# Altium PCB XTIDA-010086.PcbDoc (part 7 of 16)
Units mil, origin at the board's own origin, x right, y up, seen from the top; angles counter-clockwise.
Board outline 14763.78 x 8267.72 mil, 6 copper layers (Top Layer, GND Layer, Signal Layer 1, Signal Layer 2, Power Layer, Bottom Layer), stack 62 mil thick; 1933 components, 1002 nets, 4886 pads, 6482 vias.
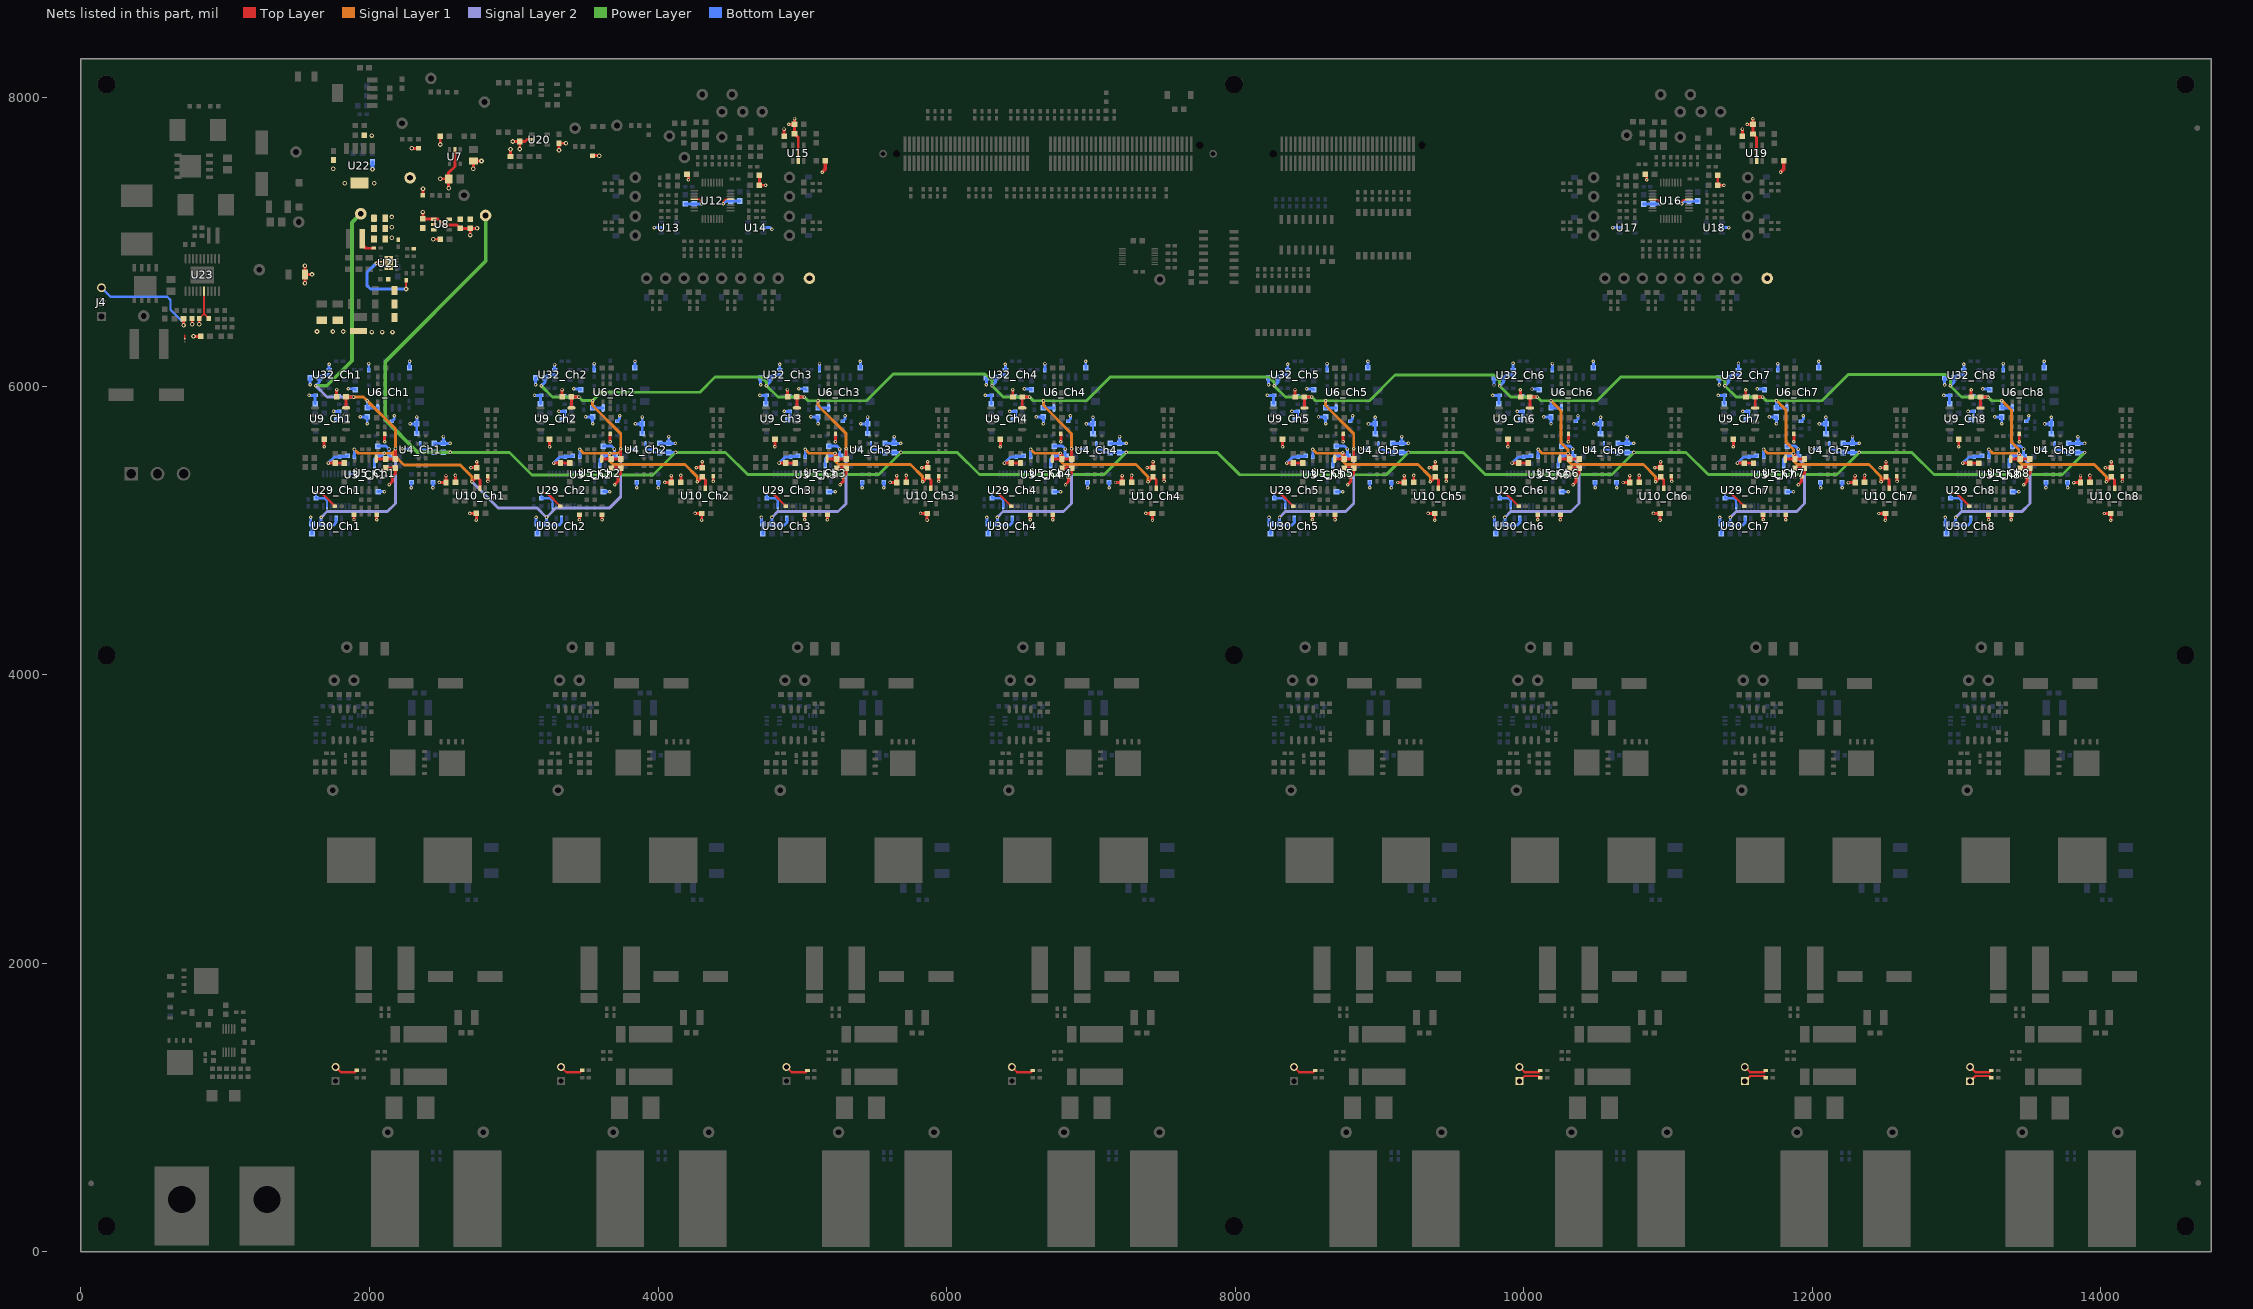
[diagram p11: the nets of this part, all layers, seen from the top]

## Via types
v1: diameter 32, hole 16, Top Layer to Bottom Layer, tented both sides, 4685 vias
v2: diameter 24, hole 12, Top Layer to Bottom Layer, tented both sides, 1013 vias
v3: diameter 32, hole 16, Top Layer to Bottom Layer, 728 vias
v4: diameter 19.68, hole 7.87, Top Layer to Bottom Layer, 40 vias
v5: diameter 214.57, hole 140, Top Layer to Bottom Layer, 16 vias

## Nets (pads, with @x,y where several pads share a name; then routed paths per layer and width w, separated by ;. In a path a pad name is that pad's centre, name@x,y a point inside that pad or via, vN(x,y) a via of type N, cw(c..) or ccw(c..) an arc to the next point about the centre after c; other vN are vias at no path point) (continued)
+VSense_Ch6: J2_Ch6.1 R14_Ch6.2 | length 166.4
  Top Layer w15: J2_Ch6.1@9969.7,1182.39 10006.41,1219.11 10103.21,1219.11 R14_Ch6.2@10115.71,1206.61
+VSense_Ch7: J2_Ch7.1 R14_Ch7.2 | length 166.4
  Top Layer w15: J2_Ch7.1@11531.7,1182.32 11568.41,1219.03 11665.21,1219.03 R14_Ch7.2@11677.71,1206.53
+VSense_Ch8: J2_Ch8.1 R14_Ch8.2 | length 166.4
  Top Layer w15: J2_Ch8.1@13093.7,1182.24 13130.41,1218.95 13227.21,1218.95 R14_Ch8.2@13239.71,1206.45
-2P5V: C39_Ch1.1 C39_Ch2.1 C39_Ch3.1 C39_Ch4.1 C39_Ch5.1 C39_Ch6.1 C39_Ch7.1 C39_Ch8.1 C43_Ch1.1 C43_Ch2.1 C43_Ch3.1 C43_Ch4.1 C43_Ch5.1 C43_Ch6.1 C43_Ch7.1 C43_Ch8.1 C133.1 C134.1 TP30.1 U4_Ch1.2 U4_Ch2.2 U4_Ch3.2 U4_Ch4.2 U4_Ch5.2 U4_Ch6.2 U4_Ch7.2 U4_Ch8.2 U8.5 | length 16495.8
  Power Layer w20: v2(2559.5,5540.2) 2969.8,5540.2 3127,5383 3964.37,5383 v2(4121.5,5540.13) 4467.87,5540.13 4622,5386 5529.45,5386 v2(5683.5,5540.05) 6073.95,5540.05 6227,5387 7092.53,5387 v2(7245.5,5539.97) 7876.03,5539.97 8031,5385 9046.31,5385 v2(9201.2,5539.89) 9580.11,5539.89 9733,5387 10610.39,5387 v2(10763.2,5539.81) 11125.19,5539.81 11279,5386 12171.46,5386 v2(12325.2,5539.73) 12689.27,5539.73 12843,5386 13733.54,5386 v2(13887.2,5539.65)
  Power Layer w25: v2(2559.5,5540.2) 2335.8,5540.2 2108.38,5767.62 2108.38,6167.38 2805,6864 TP30.1@2805,7182.7
  Bottom Layer w15: U4_Ch1.2@2352,5601.34 2352,5566.7 2359,5559.7 2393,5559.7 2412.5,5540.2 C43_Ch1.1@2449,5540.2 ; U4_Ch2.2@3914,5601.26 3914,5566.62 3921,5559.62 3955,5559.62 3974.5,5540.13 C43_Ch2.1@4011,5540.13 ; U4_Ch3.2@5476,5601.18 5476,5566.54 5483,5559.54 5517,5559.54 5536.5,5540.05 C43_Ch3.1@5573,5540.05 ; U4_Ch4.2@7038,5601.1 7038,5566.46 7045,5559.46 7079,5559.46 7098.5,5539.97 C43_Ch4.1@7135,5539.97 ; U4_Ch5.2@8993.7,5601.02 8993.7,5566.39 9000.7,5559.39 9034.7,5559.39 9054.2,5539.89 C43_Ch5.1@9090.7,5539.89 ; U4_Ch6.2@10555.7,5600.94 10555.7,5566.31 10562.7,5559.31 10596.7,5559.31 10616.2,5539.81 C43_Ch6.1@10652.7,5539.81 ; U4_Ch7.2@12117.7,5600.87 12117.7,5566.23 12124.7,5559.23 12158.7,5559.23 12178.2,5539.73 C43_Ch7.1@12214.7,5539.73 ; U4_Ch8.2@13679.7,5600.79 13679.7,5566.15 13686.7,5559.15 13720.7,5559.15 13740.2,5539.65 C43_Ch8.1@13776.7,5539.65
  Bottom Layer w20: C43_Ch1.1@2449,5540.2 C39_Ch1.1@2512.56,5540.2 v2(2559.5,5540.2) ; C43_Ch2.1@4011,5540.13 C39_Ch2.1@4074.56,5540.13 v2(4121.5,5540.13) ; C43_Ch3.1@5573,5540.05 C39_Ch3.1@5636.56,5540.05 v2(5683.5,5540.05) ; C43_Ch4.1@7135,5539.97 C39_Ch4.1@7198.56,5539.97 v2(7245.5,5539.97) ; C43_Ch5.1@9090.7,5539.89 C39_Ch5.1@9154.26,5539.89 v2(9201.2,5539.89) ; C43_Ch6.1@10652.7,5539.81 C39_Ch6.1@10716.26,5539.81 v2(10763.2,5539.81) ; C43_Ch7.1@12214.7,5539.73 C39_Ch7.1@12278.26,5539.73 v2(12325.2,5539.73) ; C43_Ch8.1@13776.7,5539.65 C39_Ch8.1@13840.26,5539.65 v2(13887.2,5539.65)
-5V: C18_Ch1.1 C18_Ch2.1 C18_Ch3.1 C18_Ch4.1 C18_Ch5.1 C18_Ch6.1 C18_Ch7.1 C18_Ch8.1 C20_Ch1.1 C20_Ch2.1 C20_Ch3.1 C20_Ch4.1 C20_Ch5.1 C20_Ch6.1 C20_Ch7.1 C20_Ch8.1 C33_Ch1.1 C33_Ch2.1 C33_Ch3.1 C33_Ch4.1 C33_Ch5.1 C33_Ch6.1 C33_Ch7.1 C33_Ch8.1 C40_Ch1.1 C40_Ch2.1 C40_Ch3.1 C40_Ch4.1 C40_Ch5.1 C40_Ch6.1 C40_Ch7.1 C40_Ch8.1 C45_Ch1.1 C45_Ch2.1 C45_Ch3.1 C45_Ch4.1 C45_Ch5.1 C45_Ch6.1 C45_Ch7.1 C45_Ch8.1 C47_Ch1.1 C47_Ch2.1 C47_Ch3.1 C47_Ch4.1 C47_Ch5.1 C47_Ch6.1 C47_Ch7.1 C47_Ch8.1 C131.1 C136_Ch1.1 C136_Ch2.1 C136_Ch3.1 C136_Ch4.1 C136_Ch5.1 C136_Ch6.1 C136_Ch7.1 C136_Ch8.1 C160.1 C161.1 C162.1 C166_Ch1.1 C166_Ch2.1 C166_Ch3.1 C166_Ch4.1 C166_Ch5.1 C166_Ch6.1 C166_Ch7.1 C166_Ch8.1 L6.2 R76_Ch1.2 R76_Ch2.2 R76_Ch3.2 R76_Ch4.2 R76_Ch5.2 R76_Ch6.2 R76_Ch7.2 R76_Ch8.2 R193_Ch1.1 R193_Ch2.1 R193_Ch3.1 R193_Ch4.1 R193_Ch5.1 R193_Ch6.1 R193_Ch7.1 R193_Ch8.1 R196.1 TP26.1 U3_Ch1.5 U3_Ch2.5 U3_Ch3.5 U3_Ch4.5 U3_Ch5.5 U3_Ch6.5 U3_Ch7.5 U3_Ch8.5 U5_Ch1.2 U5_Ch2.2 U5_Ch3.2 U5_Ch4.2 U5_Ch5.2 U5_Ch6.2 U5_Ch7.2 U5_Ch8.2 U6_Ch1.4 U6_Ch2.4 U6_Ch3.4 U6_Ch4.4 U6_Ch5.4 U6_Ch6.4 U6_Ch7.4 U6_Ch8.4 U8.2 U8.3 U9_Ch1.4 U9_Ch2.4 U9_Ch3.4 U9_Ch4.4 U9_Ch5.4 U9_Ch6.4 U9_Ch7.4 U9_Ch8.4 U10_Ch1.2 U10_Ch2.2 U10_Ch3.2 U10_Ch4.2 U10_Ch5.2 U10_Ch6.2 U10_Ch7.2 U10_Ch8.2 U30_Ch1.2 U30_Ch2.2 U30_Ch3.2 U30_Ch4.2 U30_Ch5.2 U30_Ch6.2 U30_Ch7.2 U30_Ch8.2 U32_Ch1.2 U32_Ch2.2 U32_Ch3.2 U32_Ch4.2 U32_Ch5.2 U32_Ch6.2 U32_Ch7.2 U32_Ch8.2 | length 41939.2
  Top Layer w20: C47_Ch1.1@1837.5,5924.7 C47_Ch1.1@1838.28,5923.91 ; U9_Ch1.4@1838.28,5848.55 C47_Ch1.1@1838.28,5923.91 ; v2(1889.79,5923.91) C47_Ch1.1@1838.28,5923.91 ; L6.2@1949.5,7020 1949.5,6979.5 1974,6955 2029.38,6955 R196.1@2031.38,6957 ; U3_Ch1.5@2047,5494.33 2113.79,5494.33 C20_Ch1.1@2114,5494.54 C18_Ch1.1@2180,5494.54 v2(2180,5566.49) ; v2(2710.25,5337.32) C45_Ch1.1@2744.6,5371.67 2766.54,5349.72 U10_Ch1.2@2766.54,5292.43 ; C47_Ch2.1@3399.5,5924.62 C47_Ch2.1@3400.28,5923.83 ; U9_Ch2.4@3400.28,5848.47 C47_Ch2.1@3400.28,5923.83 ; v2(3451.79,5923.83) C47_Ch2.1@3400.28,5923.83 ; U3_Ch2.5@3609,5494.25 3675.79,5494.25 C20_Ch2.1@3676,5494.46 C18_Ch2.1@3742,5494.46 v2(3742,5566.41) ; v2(4272.25,5337.24) C45_Ch2.1@4306.6,5371.59 4328.54,5349.65 U10_Ch2.2@4328.54,5292.35 ; C47_Ch3.1@4961.5,5924.54 C47_Ch3.1@4962.28,5923.76 ; U9_Ch3.4@4962.28,5848.39 C47_Ch3.1@4962.28,5923.76 ; v2(5013.79,5923.76) C47_Ch3.1@4962.28,5923.76 ; U3_Ch3.5@5171,5494.17 5237.79,5494.17 C20_Ch3.1@5238,5494.39 ; v2(5226.79,5534.54) 5238,5523.33 C20_Ch3.1@5238,5494.39 ; v2(5304,5566.33) C18_Ch3.1@5304,5494.39 C20_Ch3.1@5238,5494.39 ; v2(5834.25,5337.17) C45_Ch3.1@5868.6,5371.51 5890.54,5349.57 U10_Ch3.2@5890.54,5292.28 ; C47_Ch4.1@6523.5,5924.46 C47_Ch4.1@6524.28,5923.68 ; U9_Ch4.4@6524.28,5848.31 C47_Ch4.1@6524.28,5923.68 ; v2(6575.79,5923.68) C47_Ch4.1@6524.28,5923.68 ; U3_Ch4.5@6733,5494.09 6799.79,5494.09 C20_Ch4.1@6800,5494.31 ; v2(6788.79,5534.46) 6800,5523.25 C20_Ch4.1@6800,5494.31 ; v2(6866,5566.25) C18_Ch4.1@6866,5494.31 C20_Ch4.1@6800,5494.31 ; v2(7396.25,5337.09) C45_Ch4.1@7430.6,5371.43 7452.54,5349.49 U10_Ch4.2@7452.54,5292.2 ; C47_Ch5.1@8479.2,5924.39 C47_Ch5.1@8479.98,5923.6 ; U9_Ch5.4@8479.98,5848.24 C47_Ch5.1@8479.98,5923.6 ; v2(8531.49,5923.6) C47_Ch5.1@8479.98,5923.6 ; U3_Ch5.5@8688.7,5494.02 8755.49,5494.02 C20_Ch5.1@8755.7,5494.23 ; v2@8744.7,5536.39 8755.7,5525.39 C20_Ch5.1@8755.7,5494.23 ; v2(8821.7,5566.17) C18_Ch5.1@8821.7,5494.23 C20_Ch5.1@8755.7,5494.23 ; v2(9351.95,5337.01) C45_Ch5.1@9386.3,5371.36 9408.24,5349.41 U10_Ch5.2@9408.24,5292.12 ; C47_Ch6.1@10041.2,5924.31 C47_Ch6.1@10041.98,5923.52 ; U9_Ch6.4@10041.98,5848.16 C47_Ch6.1@10041.98,5923.52 ; v2(10093.49,5923.52) C47_Ch6.1@10041.98,5923.52 ; U3_Ch6.5@10250.7,5493.94 10317.49,5493.94 C20_Ch6.1@10317.7,5494.15 ; v2(10306.7,5532.31) 10317.7,5521.31 C20_Ch6.1@10317.7,5494.15 ; C18_Ch6.1@10383.7,5494.15 C20_Ch6.1@10317.7,5494.15 ; v2(10913.95,5336.93) C45_Ch6.1@10948.3,5371.28 10970.24,5349.33 U10_Ch6.2@10970.24,5292.04 ; C47_Ch7.1@11603.2,5924.23 C47_Ch7.1@11603.98,5923.44 ; U9_Ch7.4@11603.98,5848.08 C47_Ch7.1@11603.98,5923.44 ; v2(11655.49,5923.44) C47_Ch7.1@11603.98,5923.44 ; U3_Ch7.5@11812.7,5493.86 11879.49,5493.86 C20_Ch7.1@11879.7,5494.07 ; v2(11868.7,5532.23) 11879.7,5521.23 C20_Ch7.1@11879.7,5494.07 ; C18_Ch7.1@11945.7,5494.07 C20_Ch7.1@11879.7,5494.07 ; v2(12475.95,5336.85) C45_Ch7.1@12510.3,5371.2 12532.24,5349.25 U10_Ch7.2@12532.24,5291.96 ; C47_Ch8.1@13165.2,5924.15 C47_Ch8.1@13165.98,5923.36 ; U9_Ch8.4@13165.98,5848 C47_Ch8.1@13165.98,5923.36 ; v2(13217.49,5923.36) C47_Ch8.1@13165.98,5923.36 ; U3_Ch8.5@13374.7,5493.78 13441.49,5493.78 C20_Ch8.1@13441.7,5493.99 ; v2(13430.7,5532.15) 13436,5526.85 13436,5499.69 C20_Ch8.1@13441.7,5493.99 ; C18_Ch8.1@13507.7,5493.99 C20_Ch8.1@13441.7,5493.99 ; v2(14037.95,5336.77) C45_Ch8.1@14072.3,5371.12 14094.24,5349.17 U10_Ch8.2@14094.24,5291.88
  Power Layer w20: v2(3190.62,6001.68) 3268.46,5923.83 v2(3451.79,5923.83) ; v2@3451.79,5925.41 v2(3451.79,5923.83) ; v2(4750.73,6002.07) 4750.73,6028.27 4716,6063 4396,6063 4290,5957 3605.38,5957 v2(3547,5898.62) 3477,5898.62 v2(3451.79,5923.83) ; v2@4752.62,6001.6 4830.46,5923.76 v2(5013.79,5923.76) ; v2@5013.79,5925.33 v2(5013.79,5923.76) ; v2@6575.79,5925.25 v2(6575.79,5923.68) ; v2@8531.49,5925.17 v2(8531.49,5923.6) ; v2@10093.49,5925.09 v2(10093.49,5923.52) ; v2@11655.49,5925.02 v2(11655.49,5923.44) ; v2(13312.7,5898.15) 13242.7,5898.15 v2(13217.49,5923.36) 13034.17,5923.36 v2(12956.32,6001.2) 12956.32,6047.68 12924,6080 12249,6080 12067.23,5898.23 v2(11750.7,5898.23) 11680.7,5898.23 v2(11655.49,5923.44) ; v2(5013.79,5923.76) 5039,5898.54 v2(5109,5898.54) 5444.54,5898.54 5630,6084 6267,6084 6314.62,6036.38 v2(6314.62,6001.52) 6392.46,5923.68 v2(6575.79,5923.68) ; v2(6575.79,5923.68) 6601,5898.46 v2(6671,5898.46) 6969.46,5898.46 7133.94,6062.94 8234.06,6062.94 8270.32,6026.68 v2(8270.32,6001.44) 8348.17,5923.6 v2(8531.49,5923.6) ; v2(8531.49,5923.6) 8556.7,5898.39 v2(8626.7,5898.39) 8930.39,5898.39 9108,6076 9793,6076 9833.08,6035.92 v2(9833.08,6000.61) 9910.17,5923.52 v2(10093.49,5923.52) ; v2(10093.49,5923.52) 10118.7,5898.31 v2(10188.7,5898.31) 10507.31,5898.31 10673,6064 11362,6064 11394.32,6031.68 v2(11394.32,6001.28) 11472.17,5923.44 v2(11655.49,5923.44)
  Power Layer w25: v2(1628.38,6002) 1705,6002 1879,6176 1879,7133 TP26.1@1940,7194
  Signal Layer 1 w20: v2(1889.79,5923.91) 1959.79,5923.91 v2(1985,5898.7) 2180,5703.7 v2(2180,5566.49) 2180,5556 2158.7,5534.7 ; v2(1896,5561.07) 1922.37,5534.7 v2(2102.79,5534.7) 2158.7,5534.7 ; v2(2710.25,5337.32) 2710.25,5371.92 2629.17,5453 2240.4,5453 2158.7,5534.7 ; v2(3458,5561) 3484.37,5534.62 v2(3664.79,5534.62) ; v2(3547,5898.62) 3547,5865 3742,5670 v2(3742,5566.41) 3742,5550 3726.62,5534.62 v2(3664.79,5534.62) ; v2(4272.25,5337.24) 4272.25,5371.84 4188.09,5456 3689,5456 3664.79,5480.21 v2(3664.79,5534.62) ; v2(5020,5560.92) 5046.37,5534.54 v2(5226.79,5534.54) 5226.79,5480.13 5251,5455.92 5750.09,5455.92 5834.25,5371.77 v2(5834.25,5337.17) ; v2(5109,5898.54) 5109,5864.92 5304,5669.92 v2(5304,5566.33) ; v2(6582,5560.84) 6608.37,5534.46 v2(6788.79,5534.46) 6788.79,5480.06 6813,5455.84 7312.09,5455.84 7396.25,5371.69 v2(7396.25,5337.09) ; v2(6671,5898.46) 6671,5864.84 6866,5669.84 v2(6866,5566.25) ; v2(8537.7,5560.76) 8564.07,5534.39 8744.49,5534.39 8744.49,5479.98 8768.7,5455.76 9267.8,5455.76 9351.95,5371.61 v2(9351.95,5337.01) ; v2(8626.7,5898.39) 8626.7,5864.76 8821.7,5669.76 v2(8821.7,5566.17) ; v2(10099.7,5560.68) 10126.07,5534.31 10306.49,5534.31 10306.49,5479.9 10330.7,5455.69 10829.8,5455.69 10913.95,5371.53 v2(10913.95,5336.93) ; v2(10188.7,5898.31) 10256.7,5830.31 10256.7,5608.5 10306.7,5558.5 v2(10306.7,5532.31) ; v2(11661.7,5560.6) 11688.07,5534.23 v2@11868.49,5534.23 ; v2@11750.49,5900.23 11818.49,5832.23 11818.49,5610.42 11868.49,5560.42 v2@11868.49,5534.23 ; v2(12475.95,5336.85) 12475.95,5371.45 12391.8,5455.61 11892.7,5455.61 11868.49,5479.82 v2@11868.49,5534.23 ; v2(13223.7,5560.52) 13250.07,5534.15 v2@13430.49,5534.15 ; v2@13312.49,5900.15 13380.49,5832.15 13380.49,5610.34 13430.49,5560.34 v2@13430.49,5534.15 ; v2(14037.95,5336.77) 14037.95,5371.37 13953.8,5455.53 13454.7,5455.53 13430.49,5479.74 v2@13430.49,5534.15
  Signal Layer 2 w20: v2(1628.38,6002) 1706.46,5923.91 v2(1889.79,5923.91) ; v2(1665.5,5090) 1705.5,5130 2124,5130 2180,5186 v2(2180,5566.49) ; v2(2710.25,5337.32) 2891.57,5156 3161.42,5156 v2(3227.5,5089.92) 3293.57,5156 3665,5156 3742,5233 v2(3742,5566.41) ; v2(4789.5,5089.84) 4829.5,5129.84 5248,5129.84 5304,5185.84 v2(5304,5566.33) ; v2(6351.5,5089.76) 6391.5,5129.76 6810,5129.76 6866,5185.76 v2(6866,5566.25) ; v2(8307.2,5089.69) 8347.2,5129.69 8765.7,5129.69 8821.7,5185.69 v2(8821.7,5566.17) ; v2(9869.2,5089.61) 9909.2,5129.61 10327.7,5129.61 10383.7,5185.61 10383.7,5455.31 v2(10306.7,5532.31) ; v2(11431.2,5089.53) 11471.2,5129.53 11889.7,5129.53 11945.7,5185.53 11945.7,5455.23 v2(11868.7,5532.23) ; v2(12993.2,5089.45) 13033.2,5129.45 13451.7,5129.45 13507.7,5185.45 13507.7,5455.15 v2(13430.7,5532.15)
  Bottom Layer w20: v2(1628.38,6002) 1653.5,6027.12 C166_Ch1.1@1653.5,6057 1673.73,6077.24 U32_Ch1.2@1721.87,6077.24 ; v2@1665.5,5087.5 C136_Ch1.1@1665.5,5045 1672.5,5038 1753,5038 1769,5054 U30_Ch1.2@1769,5084.13 ; R76_Ch1.2@1786.62,5934.7 1797.41,5923.91 v2(1889.79,5923.91) ; R193_Ch1.1@1896,5509.62 v2(1896,5561.07) ; v2(1985,5898.7) C40_Ch1.1@1985,5849.54 1985.78,5848.76 U6_Ch1.4@2058,5848.76 ; U5_Ch1.2@2035,5449.18 2035,5495.55 C33_Ch1.1@2059,5519.55 2087.64,5519.55 v2(2102.79,5534.7) ; v2(3190.62,6001.68) 3215.74,6026.8 C166_Ch2.1@3215.74,6056.68 3235.98,6076.91 U32_Ch2.2@3284.11,6076.91 ; v2@3227.5,5087.43 C136_Ch2.1@3227.5,5044.92 3234.5,5037.92 3315,5037.92 3331,5053.92 U30_Ch2.2@3331,5084.06 ; R76_Ch2.2@3348.62,5934.62 3359.41,5923.83 v2(3451.79,5923.83) ; R193_Ch2.1@3458,5509.54 v2(3458,5561) ; v2(3547,5898.62) C40_Ch2.1@3547,5849.46 3547.78,5848.68 U6_Ch2.4@3620,5848.68 ; U5_Ch2.2@3597,5449.1 3597,5495.47 C33_Ch2.1@3621,5519.47 3649.64,5519.47 v2(3664.79,5534.62) ; v2(4750.73,6002.07) 4775.85,6027.19 C166_Ch3.1@4775.85,6057.07 4796.09,6077.31 U32_Ch3.2@4844.22,6077.31 ; v2@4789.5,5087.35 C136_Ch3.1@4789.5,5044.84 4796.5,5037.84 4877,5037.84 4893,5053.84 U30_Ch3.2@4893,5083.98 ; R76_Ch3.2@4910.62,5934.54 4921.41,5923.76 v2(5013.79,5923.76) ; R193_Ch3.1@5020,5509.46 v2(5020,5560.92) ; v2(5109,5898.54) C40_Ch3.1@5109,5849.39 5109.78,5848.61 U6_Ch3.4@5182,5848.61 ; U5_Ch3.2@5159,5449.02 5159,5495.39 C33_Ch3.1@5183,5519.39 5211.64,5519.39 v2(5226.79,5534.54) ; v2(6314.62,6001.52) 6339.74,6026.64 C166_Ch4.1@6339.74,6056.52 6359.98,6076.76 U32_Ch4.2@6408.11,6076.76 ; v2@6351.5,5087.27 C136_Ch4.1@6351.5,5044.76 6358.5,5037.76 6439,5037.76 6455,5053.76 U30_Ch4.2@6455,5083.9 ; R76_Ch4.2@6472.62,5934.46 6483.41,5923.68 v2(6575.79,5923.68) ; R193_Ch4.1@6582,5509.39 v2(6582,5560.84) ; v2(6671,5898.46) C40_Ch4.1@6671,5849.31 6671.78,5848.53 U6_Ch4.4@6744,5848.53 ; U5_Ch4.2@6721,5448.94 6721,5495.31 C33_Ch4.1@6745,5519.31 6773.64,5519.31 v2(6788.79,5534.46) ; v2(8270.32,6001.44) 8295.44,6026.56 C166_Ch5.1@8295.44,6056.44 8315.68,6076.68 U32_Ch5.2@8363.81,6076.68 ; v2@8307.2,5087.19 C136_Ch5.1@8307.2,5044.69 8314.2,5037.69 8394.7,5037.69 8410.7,5053.69 U30_Ch5.2@8410.7,5083.82 ; R76_Ch5.2@8428.32,5934.39 8439.11,5923.6 v2(8531.49,5923.6) ; R193_Ch5.1@8537.7,5509.31 v2(8537.7,5560.76) ; v2(8626.7,5898.39) C40_Ch5.1@8626.7,5849.23 8627.48,5848.45 U6_Ch5.4@8699.7,5848.45 ; U5_Ch5.2@8676.7,5448.87 8676.7,5495.24 C33_Ch5.1@8700.7,5519.24 8729.34,5519.24 8744.7,5534.6 v2(8744.7,5537.39) ; v2(9833.08,6000.61) 9858.2,6025.72 C166_Ch6.1@9858.2,6055.61 9878.43,6075.84 U32_Ch6.2@9926.57,6075.84 ; v2@9869.2,5087.11 C136_Ch6.1@9869.2,5044.61 9876.2,5037.61 9956.7,5037.61 9972.7,5053.61 U30_Ch6.2@9972.7,5083.74 ; R76_Ch6.2@9990.32,5934.31 10001.11,5923.52 v2(10093.49,5923.52) ; R193_Ch6.1@10099.7,5509.23 v2(10099.7,5560.68) ; v2(10188.7,5898.31) C40_Ch6.1@10188.7,5849.15 10189.48,5848.37 U6_Ch6.4@10261.7,5848.37 ; U5_Ch6.2@10238.7,5448.79 10238.7,5495.16 C33_Ch6.1@10262.7,5519.16 10291.34,5519.16 10306.49,5534.31 10306.7,5534.09 v2(10306.7,5532.31) ; v2(11394.32,6001.28) 11419.44,6026.4 C166_Ch7.1@11419.44,6056.28 11439.68,6076.52 U32_Ch7.2@11487.81,6076.52 ; v2@11431.2,5087.03 C136_Ch7.1@11431.2,5044.53 11438.2,5037.53 11518.7,5037.53 11534.7,5053.53 U30_Ch7.2@11534.7,5083.66 ; R76_Ch7.2@11552.32,5934.23 11563.11,5923.44 v2(11655.49,5923.44) ; R193_Ch7.1@11661.7,5509.15 v2(11661.7,5560.6) ; v2(11750.7,5898.23) C40_Ch7.1@11750.7,5849.07 11751.48,5848.29 U6_Ch7.4@11823.7,5848.29 ; U5_Ch7.2@11800.7,5448.71 11800.7,5495.08 C33_Ch7.1@11824.7,5519.08 11853.34,5519.08 11868.49,5534.23 11868.7,5534.02 v2(11868.7,5532.23) ; v2(12956.32,6001.2) 12981.44,6026.32 C166_Ch8.1@12981.44,6056.2 13001.68,6076.44 U32_Ch8.2@13049.81,6076.44 ; v2@12993.2,5086.95 C136_Ch8.1@12993.2,5044.45 13000.2,5037.45 13080.7,5037.45 13096.7,5053.45 U30_Ch8.2@13096.7,5083.58 ; R76_Ch8.2@13114.32,5934.15 13125.11,5923.36 v2(13217.49,5923.36) ; R193_Ch8.1@13223.7,5509.07 v2(13223.7,5560.52) ; v2(13312.7,5898.15) C40_Ch8.1@13312.7,5848.99 13313.48,5848.21 U6_Ch8.4@13385.7,5848.21 ; U5_Ch8.2@13362.7,5448.63 13362.7,5495 C33_Ch8.1@13386.7,5519 13415.34,5519 13430.49,5534.15 13430.7,5533.94 v2(13430.7,5532.15)
-VSense_Ch1: J2_Ch1.2 R17_Ch1.2 | length 166.4
  Top Layer w15: J2_Ch1.2@1766,1281.21 1802.71,1244.5 1899.51,1244.5 R17_Ch1.2@1912.01,1257
-VSense_Ch2: J2_Ch2.2 R17_Ch2.2 | length 166.4
  Top Layer w15: J2_Ch2.2@3328,1281.13 3364.71,1244.42 3461.51,1244.42 R17_Ch2.2@3474.01,1256.92
-VSense_Ch3: J2_Ch3.2 R17_Ch3.2 | length 166.4
  Top Layer w15: J2_Ch3.2@4890,1281.06 4926.71,1244.34 5023.51,1244.34 R17_Ch3.2@5036.01,1256.84
-VSense_Ch4: J2_Ch4.2 R17_Ch4.2 | length 166.4
  Top Layer w15: J2_Ch4.2@6452,1280.98 6488.71,1244.26 6585.51,1244.26 R17_Ch4.2@6598.01,1256.76
-VSense_Ch5: J2_Ch5.2 R17_Ch5.2 | length 166.4
  Top Layer w15: J2_Ch5.2@8407.7,1280.9 8444.41,1244.19 8541.21,1244.19 R17_Ch5.2@8553.71,1256.69
-VSense_Ch6: J2_Ch6.2 R17_Ch6.2 | length 166.4
  Top Layer w15: J2_Ch6.2@9969.7,1280.82 10006.41,1244.11 10103.21,1244.11 R17_Ch6.2@10115.71,1256.61
-VSense_Ch7: J2_Ch7.2 R17_Ch7.2 | length 166.4
  Top Layer w15: J2_Ch7.2@11531.7,1280.74 11568.41,1244.03 11665.21,1244.03 R17_Ch7.2@11677.71,1256.53
-VSense_Ch8: J2_Ch8.2 R17_Ch8.2 | length 166.4
  Top Layer w15: J2_Ch8.2@13093.7,1280.66 13130.41,1243.95 13227.21,1243.95 R17_Ch8.2@13239.71,1256.45
AGND: C18_Ch1.2 C18_Ch2.2 C18_Ch3.2 C18_Ch4.2 C18_Ch5.2 C18_Ch6.2 C18_Ch7.2 C18_Ch8.2 C20_Ch1.2 C20_Ch2.2 C20_Ch3.2 C20_Ch4.2 C20_Ch5.2 C20_Ch6.2 C20_Ch7.2 C20_Ch8.2 C21_Ch1.1 C21_Ch2.1 C21_Ch3.1 C21_Ch4.1 C21_Ch5.1 C21_Ch6.1 C21_Ch7.1 C21_Ch8.1 C22_Ch1.2 C22_Ch2.2 C22_Ch3.2 C22_Ch4.2 C22_Ch5.2 C22_Ch6.2 C22_Ch7.2 C22_Ch8.2 C23_Ch1.2 C23_Ch2.2 C23_Ch3.2 C23_Ch4.2 C23_Ch5.2 C23_Ch6.2 C23_Ch7.2 C23_Ch8.2 C24_Ch1.2 C24_Ch2.2 C24_Ch3.2 C24_Ch4.2 C24_Ch5.2 C24_Ch6.2 C24_Ch7.2 C24_Ch8.2 C29_Ch1.2 C29_Ch2.2 C29_Ch3.2 C29_Ch4.2 C29_Ch5.2 C29_Ch6.2 C29_Ch7.2 C29_Ch8.2 C30_Ch1.2 C30_Ch2.2 C30_Ch3.2 C30_Ch4.2 C30_Ch5.2 C30_Ch6.2 C30_Ch7.2 C30_Ch8.2 C31_Ch1.2 C31_Ch2.2 C31_Ch3.2 C31_Ch4.2 C31_Ch5.2 C31_Ch6.2 C31_Ch7.2 C31_Ch8.2 C33_Ch1.2 C33_Ch2.2 C33_Ch3.2 C33_Ch4.2 C33_Ch5.2 C33_Ch6.2 C33_Ch7.2 C33_Ch8.2 C34_Ch1.2 C34_Ch2.2 C34_Ch3.2 C34_Ch4.2 C34_Ch5.2 C34_Ch6.2 C34_Ch7.2 C34_Ch8.2 C35_Ch1.1 C35_Ch2.1 C35_Ch3.1 C35_Ch4.1 C35_Ch5.1 C35_Ch6.1 C35_Ch7.1 C35_Ch8.1 C36_Ch1.2 C36_Ch2.2 C36_Ch3.2 C36_Ch4.2 C36_Ch5.2 C36_Ch6.2 C36_Ch7.2 C36_Ch8.2 C37_Ch1.2 C37_Ch2.2 C37_Ch3.2 C37_Ch4.2 C37_Ch5.2 C37_Ch6.2 C37_Ch7.2 C37_Ch8.2 C38_Ch1.2 C38_Ch2.2 C38_Ch3.2 C38_Ch4.2 C38_Ch5.2 C38_Ch6.2 C38_Ch7.2 C38_Ch8.2 C39_Ch1.2 C39_Ch2.2 C39_Ch3.2 C39_Ch4.2 C39_Ch5.2 C39_Ch6.2 C39_Ch7.2 C39_Ch8.2 C40_Ch1.2 C40_Ch2.2 C40_Ch3.2 C40_Ch4.2 C40_Ch5.2 C40_Ch6.2 C40_Ch7.2 C40_Ch8.2 C43_Ch1.2 C43_Ch2.2 C43_Ch3.2 C43_Ch4.2 C43_Ch5.2 C43_Ch6.2 C43_Ch7.2 C43_Ch8.2 C44_Ch1.2 C44_Ch2.2 C44_Ch3.2 C44_Ch4.2 C44_Ch5.2 C44_Ch6.2 C44_Ch7.2 C44_Ch8.2 C45_Ch1.2 C45_Ch2.2 C45_Ch3.2 C45_Ch4.2 C45_Ch5.2 C45_Ch6.2 C45_Ch7.2 C45_Ch8.2 C46_Ch1.1 C46_Ch2.1 C46_Ch3.1 C46_Ch4.1 C46_Ch5.1 C46_Ch6.1 C46_Ch7.1 C46_Ch8.1 C47_Ch1.2 C47_Ch2.2 C47_Ch3.2 C47_Ch4.2 C47_Ch5.2 C47_Ch6.2 C47_Ch7.2 C47_Ch8.2 C52_Ch1.2 C52_Ch2.2 C52_Ch3.2 C52_Ch4.2 C52_Ch5.2 C52_Ch6.2 C52_Ch7.2 C52_Ch8.2 C53_Ch1.2 C53_Ch2.2 C53_Ch3.2 C53_Ch4.2 C53_Ch5.2 C53_Ch6.2 C53_Ch7.2 C53_Ch8.2 C55_Ch1.1 C55_Ch2.1 C55_Ch3.1 C55_Ch4.1 C55_Ch5.1 C55_Ch6.1 C55_Ch7.1 C55_Ch8.1 C62.1 C69.2 C70.2 C75.1 C76.1 C77.2 C78.2 C79.2 C80.2 C83.1 C90.2 C91.2 C96.1 C97.1 C98.2 C99.2 C100.2 C101.2 C102.2 C103.2 C105.2 C108.2 C116.2 C117.2 C127.1 C128.1 C129.2 C130.2 C131.2 C132.2 C133.2 C134.2 C135_Ch1.2 C135_Ch2.2 C135_Ch3.2 C135_Ch4.2 C135_Ch5.2 C135_Ch6.2 C135_Ch7.2 C135_Ch8.2 C136_Ch1.2 C136_Ch2.2 C136_Ch3.2 C136_Ch4.2 C136_Ch5.2 C136_Ch6.2 C136_Ch7.2 C136_Ch8.2 C142.2 C144.2 C145.2 C146.2 C147.2 C150_Ch1.2 C150_Ch2.2 C150_Ch3.2 C150_Ch4.2 C150_Ch5.2 C150_Ch6.2 C150_Ch7.2 C150_Ch8.2 C151_Ch1.1 C151_Ch2.1 C151_Ch3.1 C151_Ch4.1 C151_Ch5.1 C151_Ch6.1 C151_Ch7.1 C151_Ch8.1 C152.2 C153.2 C154.2 C155.2 C156.2 C157.2 C158.2 C159.1 C160.2 C161.2 C162.2 C164.2 C166_Ch1.2 C166_Ch2.2 C166_Ch3.2 C166_Ch4.2 C166_Ch5.2 C166_Ch6.2 C166_Ch7.2 C166_Ch8.2 C167_Ch1.2 C167_Ch2.2 C167_Ch3.2 C167_Ch4.2 C167_Ch5.2 C167_Ch6.2 C167_Ch7.2 C167_Ch8.2 D13.1 D15.1 D17.1 J4.3 NT1.1 R37_Ch1.1 R37_Ch2.1 R37_Ch3.1 R37_Ch4.1 R37_Ch5.1 R37_Ch6.1 R37_Ch7.1 R37_Ch8.1 R46_Ch1.1 R46_Ch2.1 R46_Ch3.1 R46_Ch4.1 R46_Ch5.1 R46_Ch6.1 R46_Ch7.1 R46_Ch8.1 R49_Ch1.2 R49_Ch2.2 R49_Ch3.2 R49_Ch4.2 R49_Ch5.2 R49_Ch6.2 R49_Ch7.2 R49_Ch8.2 R62_Ch1.1 R62_Ch2.1 R62_Ch3.1 R62_Ch4.1 R62_Ch5.1 R62_Ch6.1 R62_Ch7.1 R62_Ch8.1 R63_Ch1.2 R63_Ch2.2 R63_Ch3.2 R63_Ch4.2 R63_Ch5.2 R63_Ch6.2 R63_Ch7.2 R63_Ch8.2 R71_Ch1.1 R71_Ch2.1 R71_Ch3.1 R71_Ch4.1 R71_Ch5.1 R71_Ch6.1 R71_Ch7.1 R71_Ch8.1 R79_Ch1.1 R79_Ch2.1 R79_Ch3.1 R79_Ch4.1 R79_Ch5.1 R79_Ch6.1 R79_Ch7.1 R79_Ch8.1 R153.1 R161_Ch1.1 R161_Ch2.1 R161_Ch3.1 R161_Ch4.1 R161_Ch5.1 R161_Ch6.1 R161_Ch7.1 R161_Ch8.1 R162_Ch1.2 R162_Ch2.2 R162_Ch3.2 R162_Ch4.2 R162_Ch5.2 R162_Ch6.2 R162_Ch7.2 R162_Ch8.2 R185_Ch1.1 R185_Ch2.1 R185_Ch3.1 R185_Ch4.1 R185_Ch5.1 R185_Ch6.1 R185_Ch7.1 R185_Ch8.1 R199.1 R208.1 R210.1 R213.1 TP35.1 TP37.1 TP39.1 U7.2 U8.1 U12.13 U12.28 U13.2 U14.2 U15.2 U16.13 U16.28 U17.2 U18.2 U19.2 U20.2 U21.9 U21.10 U21.13@2134,6851.98 U22.5 U23.6 U29_Ch1.8 U29_Ch1.15 U29_Ch2.8 U29_Ch2.15 U29_Ch3.8 U29_Ch3.15 U29_Ch4.8 U29_Ch4.15 U29_Ch5.8 U29_Ch5.15 U29_Ch6.8 U29_Ch6.15 U29_Ch7.8 U29_Ch7.15 U29_Ch8.8 U29_Ch8.15 U32_Ch1.3 U32_Ch2.3 U32_Ch3.3 U32_Ch4.3 U32_Ch5.3 U32_Ch6.3 U32_Ch7.3 U32_Ch8.3 | length 28130.1
  Top Layer w10: U21.10@2078.88,6842.14 2055.86,6842.14 v2(2047,6851) 2057.83,6861.83 U21.9@2078.88,6861.83 2124.16,6861.83 U21.13@2134,6851.98 ; U12.28@4252.04,7292.95 4288.04,7292.95 4292.23,7288.76 4292.4,7288.76 4300.88,7280.28 4300.88,7263.63 v2(4302.53,7263.63) v2@4306.53,7263.63 ; v2@4447.7,7263.63 v2(4451.7,7263.63) 4453.35,7263.63 4453.35,7280.28 4461.83,7288.76 4462,7288.76 4466.19,7292.95 4502.19,7292.95 U12.13@4503.1,7293.85 ; U16.28@10892.83,7293.54 10893.74,7292.63 10929.74,7292.63 10933.93,7288.45 10934.1,7288.45 10942.58,7279.97 10942.58,7263.32 v2(10944.23,7263.32) v2@10948.23,7263.32 ; v2@11089.4,7263.32 v2(11093.4,7263.32) 11095.05,7263.32 11095.05,7279.97 11103.53,7288.45 11103.71,7288.45 11107.89,7292.63 11143.89,7292.63 U16.13@11144.8,7293.54
  Top Layer w12: NT1.1@721,6326.7 721,6352.29 ; C117.2@820.5,6468.14 853.2,6500.84 854.3,6500.84 ; U23.6@854.3,6657.5 854.3,6500.84 ; C116.2@887,6468.14 854.3,6500.84
  Top Layer w15: v2(1629.36,5259) 1668.94,5259 R162_Ch1.2@1761.14,5166.8 ; v1(2254,6673) C164.2@2254,6733.38 ; v2(3191.36,5258.92) 3230.94,5258.92 R162_Ch2.2@3323.14,5166.72 ; v2(4753.36,5258.84) 4792.94,5258.84 R162_Ch3.2@4885.14,5166.64 ; v2(6315.36,5258.76) 6354.94,5258.76 R162_Ch4.2@6447.14,5166.56 ; v2(8271.06,5258.69) 8310.64,5258.69 R162_Ch5.2@8402.84,5166.48 ; v2(9833.06,5258.61) 9872.64,5258.61 R162_Ch6.2@9964.84,5166.4 ; v2(11395.06,5258.53) 11434.64,5258.53 R162_Ch7.2@11526.84,5166.32 ; v2(12957.06,5258.45) 12996.64,5258.45 R162_Ch8.2@13088.84,5166.24
  Top Layer w20: v1(712,6420.7) R208.1@712,6467.7 ; R210.1@771.3,6468.34 772,6467.64 v1(772,6428.7) ; v1(781,6344.7) 830.5,6344.7 R213.1@831.5,6345.7 R213.1@832.2,6346.4 ; v1(820.5,6429.2) C117.2@820.5,6468.14 ; v1(1552.89,6712.81) R153.1@1552.89,6773.7 ; v1(1552.89,6834.59) R153.1@1552.89,6773.7 ; v1(1602,6773.7) R153.1@1552.89,6773.7 ; v2(1686.5,5580.2) C44_Ch1.2@1686.5,5631.7 ; v2(1714.84,5466.55) C24_Ch1.2@1762,5466.55 C23_Ch1.2@1826,5466.55 ; v2(1772.79,5975.7) 1772.79,5929.99 1771,5928.2 C47_Ch1.2@1774.5,5924.7 ; v2(1893.2,5073.28) C22_Ch1.2@1893.2,5107.69 ; v2(2050.2,5073.28) C21_Ch1.1@2050.2,5107.69 ; v2(2105.79,5613.7) 2105.79,5670.21 R37_Ch1.1@2106,5670.43 ; C20_Ch1.2@2114,5431.55 C18_Ch1.2@2180,5431.55 2180,5393.59 R185_Ch1.1@2159.41,5373 2159.41,5338.41 v2(2138,5317) ; v1(2294.16,7647.57) D17.1@2340.06,7647.57 ; v1(2370,7205.7) C131.2@2370,7158.5 2371.4,7157.1 U8.1@2445.87,7157.1 2475.85,7157.1 2517.26,7115.7 2607.5,7115.7 C134.2@2630,7093.2 C133.2@2699,7093.2 ; D13.1@2371,7321.32 v1(2371,7367.22) ; v1(2443,7017.7) C132.2@2491.5,7017.7 ; v2(2484.48,5331.94) C52_Ch1.2@2530.39,5331.94 ; v1(2490,7436.32) C130.2@2549,7436.32 v1(2549,7369.85) ; v1(2490.5,7674.39) C147.2@2490.5,7731.39 ; C52_Ch1.2@2530.54,5331.8 v2(2530.54,5379.95) ; C130.2@2549,7441.32 2549,7478.32 2592,7521.32 U7.2@2592,7639.52 ; R63_Ch1.2@2596.05,5332.68 v2(2596.05,5380.84) ; v2(2695.04,5117.32) C53_Ch1.2@2740.95,5117.32 ; v1(2699,7046.24) C133.2@2699,7093.2 ; v2(2703.25,5434.66) C45_Ch1.2@2744.6,5434.66 v2(2744.6,5476.01) ; v1(2720,7505.8) C129.2@2720,7559.32 v1(2777,7559.32) ; v2(2740.95,5071.1) C53_Ch1.2@2740.95,5117.02 ; v1(2745.96,7093.2) C133.2@2699,7093.2 ; v2(2821,5339.18) R71_Ch1.1@2821,5374.46 ; C146.2@2977.5,7591 v1(2977.5,7640.82) ; v1(2992.2,7694.9) C102.2@3042.03,7694.9 ; v1(3042.03,7642.73) C102.2@3042.03,7694.9 ; U20.2@3123.89,7708.4 3092.7,7708.4 3079.2,7694.9 C102.2@3042.03,7694.9 ; v2(3248.5,5580.12) C44_Ch2.2@3248.5,5631.62 ; v2(3276.84,5466.47) C24_Ch2.2@3324,5466.47 C23_Ch2.2@3388,5466.47 ; v1(3314.03,7633.97) C103.2@3314.03,7682.9 v1(3361.8,7682.9) ; v2(3334.79,5975.62) 3334.79,5929.91 3333,5928.13 C47_Ch2.2@3336.5,5924.62 ; v2(3455.2,5073.2) C22_Ch2.2@3455.2,5107.61 ; D15.1@3546,7596.5 v1(3591.9,7596.5) ; v2(3612.2,5073.2) C21_Ch2.1@3612.2,5107.61 ; v2(3667.79,5613.62) 3667.79,5670.13 R37_Ch2.1@3668,5670.35 ; C20_Ch2.2@3676,5431.47 C18_Ch2.2@3742,5431.47 3742,5393.51 R185_Ch2.1@3721.41,5372.92 3721.41,5338.33 v2(3700,5316.92) ; v2(4046.48,5331.87) C52_Ch2.2@4092.39,5331.87 ; C52_Ch2.2@4092.54,5331.72 v2(4092.54,5379.87) ; R63_Ch2.2@4158.05,5332.6 v2(4158.05,5380.76) ; C62.1@4201.12,7469.01 4210.53,7459.61 v2(4210.53,7429.63) ; v2(4257.04,5117.24) C53_Ch2.2@4302.95,5117.24 ; v2(4265.25,5434.58) C45_Ch2.2@4306.6,5434.58 v2(4306.6,5475.93) ; v2(4302.95,5071.03) C53_Ch2.2@4302.95,5116.94 ; v2(4383,5339.1) R71_Ch2.1@4383,5374.38 ; C77.2@4702.61,7461.01 C78.2@4702.61,7392.01 4728.15,7392.01 4728.53,7391.63 v2(4745.53,7391.63) ; v2(4810.5,5580.04) C44_Ch3.2@4810.5,5631.54 ; v2(4838.84,5466.39) C24_Ch3.2@4886,5466.39 C23_Ch3.2@4950,5466.39 ; C127.1@4873.61,7732.24 v2(4873.61,7781.2) ; v2(4896.79,5975.54) 4896.79,5929.83 4895,5928.05 C47_Ch3.2@4898.5,5924.54 ; v2(4906.34,7813.48) C79.2@4946.34,7813.48 ; v2(4946.34,7853.48) C79.2@4946.34,7813.48 ; U15.2@4972.33,7560.35 4971.77,7560.35 4971.77,7722.05 C80.2@4946.34,7747.48 C79.2@4946.34,7813.48 ; v2(5017.2,5073.13) C22_Ch3.2@5017.2,5107.53 ; v2(5174.2,5073.13) C21_Ch3.1@5174.2,5107.53 ; v2(5229.79,5613.54) 5229.79,5670.06 R37_Ch3.1@5230,5670.27 ; C20_Ch3.2@5238,5431.39 C18_Ch3.2@5304,5431.39 5304,5393.43 R185_Ch3.1@5283.41,5372.84 5283.41,5338.25 v2(5262,5316.84) ; v2(5608.48,5331.79) C52_Ch3.2@5654.39,5331.79 ; C52_Ch3.2@5654.54,5331.64 v2(5654.54,5379.8) ; R63_Ch3.2@5720.05,5332.52 v2(5720.05,5380.68) ; v2(5819.04,5117.16) C53_Ch3.2@5864.95,5117.16 ; v2(5827.25,5434.51) C45_Ch3.2@5868.6,5434.51 v2(5868.6,5475.85) ; v2(5864.95,5070.95) C53_Ch3.2@5864.95,5116.86 ; v2(5945,5339.03) R71_Ch3.1@5945,5374.3 ; v2(6372.5,5579.96) C44_Ch4.2@6372.5,5631.46 ; v2(6400.84,5466.32) C24_Ch4.2@6448,5466.32 C23_Ch4.2@6512,5466.32 ; v2(6458.79,5975.46) 6458.79,5929.76 6457,5927.97 C47_Ch4.2@6460.5,5924.46 ; v2(6579.2,5073.05) C22_Ch4.2@6579.2,5107.45 ; v2(6736.2,5073.05) C21_Ch4.1@6736.2,5107.45 ; v2(6791.79,5613.46) 6791.79,5669.98 R37_Ch4.1@6792,5670.19 ; C20_Ch4.2@6800,5431.32 C18_Ch4.2@6866,5431.32 6866,5393.35 R185_Ch4.1@6845.41,5372.76 6845.41,5338.17 v2(6824,5316.76) ; v2(7170.48,5331.71) C52_Ch4.2@7216.39,5331.71 ; C52_Ch4.2@7216.54,5331.56 v2(7216.54,5379.72) ; R63_Ch4.2@7282.05,5332.44 v2(7282.05,5380.6) ; v2(7381.04,5117.08) C53_Ch4.2@7426.95,5117.08 ; v2(7389.25,5434.43) C45_Ch4.2@7430.6,5434.43 v2(7430.6,5475.77) ; v2(7426.95,5070.87) C53_Ch4.2@7426.95,5116.78 ; v2(7507,5338.95) R71_Ch4.1@7507,5374.22 ; v2(8328.2,5579.88) C44_Ch5.2@8328.2,5631.39 ; v2(8356.54,5466.24) C24_Ch5.2@8403.7,5466.24 C23_Ch5.2@8467.7,5466.24 ; v2(8414.49,5975.39) 8414.49,5929.68 8412.7,5927.89 C47_Ch5.2@8416.2,5924.39 ; v2(8534.91,5072.97) C22_Ch5.2@8534.91,5107.37 ; v2(8691.91,5072.97) C21_Ch5.1@8691.91,5107.37 ; v2(8747.49,5613.39) 8747.49,5669.9 R37_Ch5.1@8747.7,5670.11 ; C20_Ch5.2@8755.7,5431.24 C18_Ch5.2@8821.7,5431.24 8821.7,5393.28 R185_Ch5.1@8801.11,5372.69 8801.11,5338.09 v2(8779.7,5316.69) ; v2(9126.18,5331.63) C52_Ch5.2@9172.1,5331.63 ; C52_Ch5.2@9172.24,5331.48 v2(9172.24,5379.64) ; R63_Ch5.2@9237.75,5332.36 v2(9237.75,5380.52) ; v2(9336.74,5117) C53_Ch5.2@9382.65,5117 ; v2(9344.95,5434.35) C45_Ch5.2@9386.3,5434.35 v2(9386.3,5475.7) ; v2(9382.65,5070.79) C53_Ch5.2@9382.65,5116.7 ; v2(9462.7,5338.87) R71_Ch5.1@9462.7,5374.14 ; v2(9890.2,5579.8) C44_Ch6.2@9890.2,5631.31 ; v2(9918.54,5466.16) C24_Ch6.2@9965.7,5466.16 C23_Ch6.2@10029.7,5466.16 ; v2(9976.49,5975.31) 9976.49,5929.6 9974.7,5927.81 C47_Ch6.2@9978.2,5924.31 ; v2(10096.91,5072.89) C22_Ch6.2@10096.91,5107.29 ; v2(10253.91,5072.89) C21_Ch6.1@10253.91,5107.29 ; v2(10309.49,5613.31) 10309.49,5669.82 R37_Ch6.1@10309.7,5670.03 ; C20_Ch6.2@10317.7,5431.16 C18_Ch6.2@10383.7,5431.16 10383.7,5393.2 R185_Ch6.1@10363.11,5372.61 10363.11,5338.02 v2(10341.7,5316.61) ; v2(10688.18,5331.55) C52_Ch6.2@10734.1,5331.55 ; C52_Ch6.2@10734.24,5331.4 v2(10734.24,5379.56) ; R63_Ch6.2@10799.75,5332.28 v2(10799.75,5380.44) ; C83.1@10842.82,7468.7 10852.23,7459.29 v2(10852.23,7429.32) ; v2(10898.74,5116.92) C53_Ch6.2@10944.65,5116.92 ; v2(10906.95,5434.27) C45_Ch6.2@10948.3,5434.27 v2(10948.3,5475.62) ; v2(10944.65,5070.71) C53_Ch6.2@10944.65,5116.62 ; v2(11024.7,5338.79) R71_Ch6.1@11024.7,5374.06 ; C98.2@11344.31,7460.7 C99.2@11344.31,7391.7 11369.85,7391.7 11370.23,7391.32 v2(11387.23,7391.32) ; v2(11452.2,5579.72) C44_Ch7.2@11452.2,5631.23 ; v2(11480.54,5466.08) C24_Ch7.2@11527.7,5466.08 C23_Ch7.2@11591.7,5466.08 ; C128.1@11515.29,7731.95 v2(11515.29,7780.91) ; v2(11538.49,5975.23) 11538.49,5929.52 11536.7,5927.73 C47_Ch7.2@11540.2,5924.23 ; v2(11548.02,7813.19) C100.2@11588.02,7813.19 ; v2(11588.02,7853.19) C100.2@11588.02,7813.19 ; U19.2@11614.03,7560.03 11613.45,7560.05 11613.45,7721.76 C101.2@11588.42,7746.79 11588.02,7747.19 C100.2@11588.02,7813.19 ; v2(11658.91,5072.81) C22_Ch7.2@11658.91,5107.22 ; v2(11815.91,5072.81) C21_Ch7.1@11815.91,5107.22 ; v2(11871.49,5613.23) 11871.49,5669.74 R37_Ch7.1@11871.7,5669.95 ; C20_Ch7.2@11879.7,5431.08 C18_Ch7.2@11945.7,5431.08 11945.7,5393.12 R185_Ch7.1@11925.11,5372.53 11925.11,5337.94 v2(11903.7,5316.53) ; v2(12250.18,5331.47) C52_Ch7.2@12296.1,5331.47 ; C52_Ch7.2@12296.24,5331.32 v2(12296.24,5379.48) ; R63_Ch7.2@12361.75,5332.2 v2(12361.75,5380.36) ; v2(12460.74,5116.84) C53_Ch7.2@12506.65,5116.84 ; v2(12468.95,5434.19) C45_Ch7.2@12510.3,5434.19 v2(12510.3,5475.54) ; v2(12506.65,5070.63) C53_Ch7.2@12506.65,5116.55 ; v2(12586.7,5338.71) R71_Ch7.1@12586.7,5373.98 ; v2(13014.2,5579.65) C44_Ch8.2@13014.2,5631.15 ; v2(13042.54,5466) C24_Ch8.2@13089.7,5466 C23_Ch8.2@13153.7,5466 ; v2(13100.49,5975.15) 13100.49,5929.44 13098.7,5927.65 C47_Ch8.2@13102.2,5924.15 ; v2(13220.91,5072.73) C22_Ch8.2@13220.91,5107.14 ; v2(13377.91,5072.73) C21_Ch8.1@13377.91,5107.14 ; v2(13433.49,5613.15) 13433.49,5669.66 R37_Ch8.1@13433.7,5669.87 ; C20_Ch8.2@13441.7,5431 C18_Ch8.2@13507.7,5431 13507.7,5393.04 R185_Ch8.1@13487.11,5372.45 13487.11,5337.86 v2(13465.7,5316.45) ; v2(13812.18,5331.39) C52_Ch8.2@13858.1,5331.39 ; C52_Ch8.2@13858.24,5331.24 v2(13858.24,5379.4) ; R63_Ch8.2@13923.75,5332.13 v2(13923.75,5380.28) ; v2(14022.74,5116.76) C53_Ch8.2@14068.65,5116.76 ; v2(14030.95,5434.11) C45_Ch8.2@14072.3,5434.11 v2(14072.3,5475.46) ; v2(14068.65,5070.55) C53_Ch8.2@14068.65,5116.47 ; v2(14148.7,5338.63) R71_Ch8.1@14148.7,5373.91
  Top Layer w25: v2(5138,7482.32) 5159.5,7503.82 C144.2@5159.5,7561 ; v2(11779.57,7482.13) 11801.07,7503.63 C145.2@11801.07,7560.81
  Bottom Layer w15: J4.3@143,6682 206,6619 599,6619 621,6597 621,6529 712,6438 v1(712,6420.7) ; v2(1629.36,5259) C135_Ch1.2@1629.36,5222.56 1688.44,5222.56 1706.02,5204.98 U29_Ch1.15@1706.02,5166.8 ; U29_Ch1.8@1859.57,5391.2 1894.2,5391.2 1905,5402 v2(1905,5421) ; v2(2227.79,5564.7) 2274.72,5564.7 R49_Ch1.2@2275,5564.43 ; C30_Ch1.2@2328.5,5671.05 C31_Ch1.2@2328.5,5738.05 ; v2(3191.36,5258.92) C135_Ch2.2@3191.36,5222.48 3250.44,5222.48 3268.02,5204.9 U29_Ch2.15@3268.02,5166.72 ; U29_Ch2.8@3421.57,5391.13 3456.2,5391.13 3467,5401.92 v2(3467,5420.92) ; v2(3789.79,5564.62) 3836.72,5564.62 R49_Ch2.2@3837,5564.35 ; C30_Ch2.2@3890.5,5670.97 C31_Ch2.2@3890.5,5737.97 ; v2(4753.36,5258.84) C135_Ch3.2@4753.36,5222.4 4812.44,5222.4 4830.02,5204.82 U29_Ch3.15@4830.02,5166.64 ; U29_Ch3.8@4983.57,5391.05 5018.2,5391.05 5029,5401.84 v2(5029,5420.84) ; v2(5351.79,5564.54) 5398.72,5564.54 R49_Ch3.2@5399,5564.27 ; C30_Ch3.2@5452.5,5670.89 C31_Ch3.2@5452.5,5737.89 ; v2(6315.36,5258.76) C135_Ch4.2@6315.36,5222.32 6374.44,5222.32 6392.02,5204.74 U29_Ch4.15@6392.02,5166.56 ; U29_Ch4.8@6545.57,5390.97 6580.2,5390.97 6591,5401.76 v2(6591,5420.76) ; v2(6913.79,5564.46) 6960.72,5564.46 R49_Ch4.2@6961,5564.19 ; C30_Ch4.2@7014.5,5670.81 C31_Ch4.2@7014.5,5737.81 ; v2(8271.06,5258.69) C135_Ch5.2@8271.06,5222.24 8330.14,5222.24 8347.72,5204.66 U29_Ch5.15@8347.72,5166.48 ; U29_Ch5.8@8501.27,5390.89 8535.91,5390.89 8546.7,5401.69 v2(8546.7,5420.69) ; v2(8869.49,5564.39) 8916.43,5564.39 R49_Ch5.2@8916.7,5564.11 ; C30_Ch5.2@8970.2,5670.73 C31_Ch5.2@8970.2,5737.73 ; v2(9833.06,5258.61) C135_Ch6.2@9833.06,5222.17 9892.14,5222.17 9909.72,5204.58 U29_Ch6.15@9909.72,5166.4 ; U29_Ch6.8@10063.27,5390.81 10097.91,5390.81 10108.7,5401.61 v2(10108.7,5420.61) ; v2(10431.49,5564.31) 10478.43,5564.31 R49_Ch6.2@10478.7,5564.03 ; C30_Ch6.2@10532.2,5670.65 C31_Ch6.2@10532.2,5737.65 ; v2(11395.06,5258.53) C135_Ch7.2@11395.06,5222.09 11454.14,5222.09 11471.72,5204.5 U29_Ch7.15@11471.72,5166.32 ; U29_Ch7.8@11625.27,5390.73 11659.91,5390.73 11670.7,5401.53 v2(11670.7,5420.53) ; v2(11993.49,5564.23) 12040.43,5564.23 R49_Ch7.2@12040.7,5563.95 ; C30_Ch7.2@12094.2,5670.57 C31_Ch7.2@12094.2,5737.57 ; v2(12957.06,5258.45) C135_Ch8.2@12957.06,5222.01 13016.14,5222.01 13033.72,5204.43 U29_Ch8.15@13033.72,5166.24 ; U29_Ch8.8@13187.27,5390.65 13221.91,5390.65 13232.7,5401.45 v2(13232.7,5420.45) ; v2(13555.49,5564.15) 13602.43,5564.15 R49_Ch8.2@13602.7,5563.87 ; C30_Ch8.2@13656.2,5670.5 C31_Ch8.2@13656.2,5737.5
  Bottom Layer w20: v2(1582,5935.7) R79_Ch1.1@1628.38,5935.7 1623.72,5931.04 C55_Ch1.1@1623.72,5878.7 ; v2(1589.06,6008.8) 1589.06,6055.55 C166_Ch1.2@1590.5,6057 ; v2(1593,5090) 1593,5054.5 C136_Ch1.2@1602.5,5045 C150_Ch1.2@1602.5,4976.08 ; v2(1714.84,5466.55) 1757.54,5509.24 R161_Ch1.1@1795.38,5509.24 1797.52,5511.39 1841.25,5511.39 C151_Ch1.1@1846.98,5517.12 ; v2(1721,6151) 1721,6115.5 U32_Ch1.3@1721.87,6114.64 ; v2(1751.28,5824.7) R62_Ch1.1@1790.38,5824.7 1790.38,5781.68 C46_Ch1.1@1775.29,5766.59 ; v2(1853,5981) 1896.5,5981 C167_Ch1.2@1902,5975.5 ; v2(1935.63,5786.55) C40_Ch1.2@1985,5786.55 v2(1985,5739.7) ; C37_Ch1.2@1995.21,6110.5 v2(1995.21,6156.14) ; v2(2047,6851) 1982,6786 1982,6699 2008,6673 v1(2254,6673) ; C33_Ch1.2@2059,5582.54 2059,5585.57 2115.16,5585.57 2137.04,5563.7 v2(2135.79,5563.7) 2135.79,5517.76 R46_Ch1.1@2142,5511.54 ; C29_Ch1.2@2060.5,5268.05 v2(2103.69,5268.05) ; C38_Ch1.2@2155.62,5756.05 2172.04,5772.47 v2(2172.04,5794.7) ; C34_Ch1.2@2278.43,6126.54 v2(2278.43,6172.18) ; v2(2281.56,5738.05) C31_Ch1.2@2328.5,5738.05 v2(2328.5,5784.99) ; v2(2290,5294.7) 2290,5332.49 C35_Ch1.1@2291,5333.49 ; v2(2440,5294.7) C36_Ch1.2@2440,5332.49 C36_Ch1.2@2441,5333.49 ; C43_Ch1.2@2449,5603.2 C39_Ch1.2@2512.56,5603.2 ; v2(2512.56,5650.13) C39_Ch1.2@2512.56,5603.2 ; v2(2559.06,5603.2) C39_Ch1.2@2512.56,5603.2 ; v2(3144,5935.62) R79_Ch2.1@3190.38,5935.62 3185.72,5930.96 C55_Ch2.1@3185.72,5878.62 ; v2(3151.3,6008.47) 3151.3,6055.23 C166_Ch2.2@3152.75,6056.68 ; v2(3155,5089.92) 3155,5054.43 C136_Ch2.2@3164.5,5044.92 C150_Ch2.2@3164.5,4976 ; v2(3276.84,5466.47) 3319.54,5509.17 R161_Ch2.1@3357.38,5509.17 3359.52,5511.31 3403.25,5511.31 C151_Ch2.1@3408.98,5517.04 ; v2(3283,6149) 3283,6115.43 U32_Ch2.3@3284.11,6114.31 ; v2(3313.28,5824.62) R62_Ch2.1@3352.38,5824.62 3352.38,5781.6 C46_Ch2.1@3337.29,5766.51 ; v2(3415.24,5980.68) 3458.75,5980.68 C167_Ch2.2@3464.24,5975.18 ; v2(3497.63,5786.47) C40_Ch2.2@3547,5786.47 v2(3547,5739.62) ; C37_Ch2.2@3557.21,6110.43 v2(3557.21,6156.06) ; C33_Ch2.2@3621,5582.46 3621,5585.5 3677.16,5585.5 3699.04,5563.62 v2(3697.79,5563.62) 3697.79,5517.68 R46_Ch2.1@3704,5511.46 ; C29_Ch2.2@3622.5,5267.97 v2(3665.69,5267.97) ; C38_Ch2.2@3717.62,5755.97 3734.04,5772.39 v2(3734.04,5794.62) ; C34_Ch2.2@3840.43,6126.46 v2(3840.43,6172.1) ; v2(3843.56,5737.97) C31_Ch2.2@3890.5,5737.97 v2(3890.5,5784.91) ; v2(3853,5295.62) C35_Ch2.1@3853,5333.41 C35_Ch2.1@3854,5334.41 ; v2(3974,7098.7) U13.2@4021.87,7098.7 ; C36_Ch2.2@4002,5332.41 3998.79,5329.2 C36_Ch2.2@4003,5324.98 ; v2(4003,5295.62) C36_Ch2.2@4003,5324.98 ; C36_Ch2.2@4004,5334.41 4003,5333.41 C36_Ch2.2@4003,5324.98 ; C36_Ch2.2@4005.79,5322.2 C36_Ch2.2@4003,5324.98 ; C43_Ch2.2@4011,5603.12 C39_Ch2.2@4074.56,5603.12 ; v2(4074.56,5650.06) C39_Ch2.2@4074.56,5603.12 ; v2(4121.06,5603.12) C39_Ch2.2@4074.56,5603.12 ; C69.2@4189.11,7262.52 4250.97,7262.52 C70.2@4251.13,7262.36 4301.25,7262.36 v2(4302.53,7263.63) ; v2(4451.7,7263.63) 4470.11,7282.04 C76.1@4503.1,7282.04 4503.57,7282.52 C75.1@4565.11,7282.52 ; v2(4706,5935.54) R79_Ch3.1@4752.38,5935.54 4747.72,5930.88 C55_Ch3.1@4747.72,5878.54 ; v2(4711.41,6008.87) 4711.41,6055.62 C166_Ch3.2@4712.86,6057.07 ; v2(4717,5089.84) 4717,5054.35 C136_Ch3.2@4726.5,5044.84 C150_Ch3.2@4726.5,4975.92 ; U14.2@4731.43,7098.7 4776.9,7098.7 v2(4789.6,7086) ; v2(4838.84,5466.39) 4881.54,5509.09 R161_Ch3.1@4919.38,5509.09 4921.52,5511.23 4965.25,5511.23 C151_Ch3.1@4970.98,5516.96 ; v2(4844,6152) 4844,6114.93 U32_Ch3.3@4844.22,6114.71 ; v2(4875.28,5824.54) R62_Ch3.1@4914.38,5824.54 4914.38,5781.52 C46_Ch3.1@4899.29,5766.43 ; v2(4975.35,5981.07) 5018.86,5981.07 C167_Ch3.2@5024.35,5975.58 ; v2(5059.63,5786.39) C40_Ch3.2@5109,5786.39 v2(5109,5739.54) ; C37_Ch3.2@5119.21,6110.35 v2(5119.21,6155.98) ; C33_Ch3.2@5183,5582.39 5183,5585.42 5239.16,5585.42 5261.04,5563.54 v2(5259.79,5563.54) 5259.79,5517.6 R46_Ch3.1@5266,5511.39 ; C29_Ch3.2@5184.5,5267.89 v2(5227.69,5267.89) ; C38_Ch3.2@5279.62,5755.89 5296.04,5772.31 v2(5296.04,5794.54) ; C34_Ch3.2@5402.43,6126.39 v2(5402.43,6172.02) ; v2(5405.56,5737.89) C31_Ch3.2@5452.5,5737.89 v2(5452.5,5784.83) ; v2(5415,5295.54) C35_Ch3.1@5415,5333.33 C35_Ch3.1@5416,5334.33 ; C36_Ch3.2@5564,5332.33 5560.79,5329.12 C36_Ch3.2@5565,5324.91 ; v2(5565,5295.54) C36_Ch3.2@5565,5324.91 ; C36_Ch3.2@5566,5334.33 5565,5333.33 C36_Ch3.2@5565,5324.91 ; C36_Ch3.2@5567.79,5322.12 C36_Ch3.2@5565,5324.91 ; C43_Ch3.2@5573,5603.04 C39_Ch3.2@5636.56,5603.04 ; v2(5636.56,5649.98) C39_Ch3.2@5636.56,5603.04 ; v2(5683.06,5603.04) C39_Ch3.2@5636.56,5603.04 ; v2(6268,5935.46) R79_Ch4.1@6314.38,5935.46 6309.72,5930.8 C55_Ch4.1@6309.72,5878.46 ; v2(6275.3,6008.31) 6275.3,6055.07 C166_Ch4.2@6276.75,6056.52 ; v2(6279,5089.76) 6279,5054.27 C136_Ch4.2@6288.5,5044.76 C150_Ch4.2@6288.5,4975.84 ; v2(6400.84,5466.32) 6443.54,5509.01 R161_Ch4.1@6481.38,5509.01 6483.52,5511.15 6527.25,5511.15 C151_Ch4.1@6532.98,5516.88 ; v2(6407,6151) 6407,6115.27 U32_Ch4.3@6408.11,6114.16 ; v2(6437.28,5824.46) R62_Ch4.1@6476.38,5824.46 6476.38,5781.44 C46_Ch4.1@6461.29,5766.35 ; v2(6539.24,5980.52) 6582.75,5980.52 C167_Ch4.2@6588.24,5975.02 ; v2(6621.63,5786.32) C40_Ch4.2@6671,5786.32 v2(6671,5739.46) ; C37_Ch4.2@6681.21,6110.27 v2(6681.21,6155.91) ; C33_Ch4.2@6745,5582.31 6745,5585.34 6801.16,5585.34 6823.04,5563.46 v2(6821.79,5563.46) 6821.79,5517.52 R46_Ch4.1@6828,5511.31 ; C29_Ch4.2@6746.5,5267.81 v2(6789.69,5267.81) ; C38_Ch4.2@6841.62,5755.81 6858.04,5772.23 v2(6858.04,5794.46) ; C34_Ch4.2@6964.43,6126.31 v2(6964.43,6171.94) ; v2(6967.56,5737.81) C31_Ch4.2@7014.5,5737.81 v2(7014.5,5784.76) ; v2(6977,5295.46) C35_Ch4.1@6977,5333.25 C35_Ch4.1@6978,5334.25 ; C36_Ch4.2@7126,5332.25 7122.79,5329.04 C36_Ch4.2@7127,5324.83 ; v2(7127,5295.46) C36_Ch4.2@7127,5324.83 ; C36_Ch4.2@7128,5334.25 7127,5333.25 C36_Ch4.2@7127,5324.83 ; C36_Ch4.2@7129.79,5322.04 C36_Ch4.2@7127,5324.83 ; C43_Ch4.2@7135,5602.96 C39_Ch4.2@7198.56,5602.96 ; v2(7198.56,5649.9) C39_Ch4.2@7198.56,5602.96 ; v2(7245.06,5602.96) C39_Ch4.2@7198.56,5602.96 ; v2(8223.7,5935.39) R79_Ch5.1@8270.08,5935.39 8265.42,5930.72 C55_Ch5.1@8265.42,5878.39 ; v2(8231,6008.24) 8231,6054.99 C166_Ch5.2@8232.45,6056.44 ; v2(8234.7,5089.69) 8234.7,5054.19 C136_Ch5.2@8244.2,5044.69 C150_Ch5.2@8244.2,4975.76 ; v2(8356.54,5466.24) 8399.24,5508.93 R161_Ch5.1@8437.08,5508.93 8439.22,5511.07 8482.95,5511.07 C151_Ch5.1@8488.69,5516.8 ; U32_Ch5.3@8363.81,6114.08 8364,6114.27 v2(8364,6152) ; v2(8392.98,5824.39) R62_Ch5.1@8432.08,5824.39 8432.08,5781.36 C46_Ch5.1@8416.99,5766.28 ; v2(8494.94,5980.44) 8538.45,5980.44 C167_Ch5.2@8543.94,5974.95 ; v2(8577.33,5786.24) C40_Ch5.2@8626.7,5786.24 v2(8626.7,5739.39) ; C37_Ch5.2@8636.91,6110.19 v2(8636.91,6155.83) ; C33_Ch5.2@8700.7,5582.23 8700.7,5585.26 8756.86,5585.26 8778.74,5563.39 v2(8777.49,5563.39) 8777.49,5517.44 R46_Ch5.1@8783.7,5511.23 ; C29_Ch5.2@8702.2,5267.73 v2(8745.39,5267.73) ; C38_Ch5.2@8797.32,5755.73 8813.74,5772.15 v2(8813.74,5794.39) ; C34_Ch5.2@8920.13,6126.23 v2(8920.13,6171.87) ; v2(8923.26,5737.73) C31_Ch5.2@8970.2,5737.73 v2(8970.2,5784.68) ; v2(8932.7,5295.39) C35_Ch5.1@8932.7,5333.17 C35_Ch5.1@8933.7,5334.17 ; C36_Ch5.2@9081.7,5332.17 9078.49,5328.96 C36_Ch5.2@9082.7,5324.75 ; v2(9082.7,5295.39) C36_Ch5.2@9082.7,5324.75 ; C36_Ch5.2@9083.7,5334.17 9082.7,5333.17 C36_Ch5.2@9082.7,5324.75 ; C36_Ch5.2@9085.49,5321.96 C36_Ch5.2@9082.7,5324.75 ; C43_Ch5.2@9090.7,5602.88 C39_Ch5.2@9154.26,5602.88 ; v2(9154.26,5649.82) C39_Ch5.2@9154.26,5602.88 ; v2(9200.76,5602.88) C39_Ch5.2@9154.26,5602.88 ; v2(9785.7,5935.31) R79_Ch6.1@9832.08,5935.31 9827.42,5930.65 C55_Ch6.1@9827.42,5878.31 ; v2(9793.76,6007.4) 9793.76,6054.16 C166_Ch6.2@9795.2,6055.61 ; v2(9796.7,5089.61) 9796.7,5054.11 C136_Ch6.2@9806.2,5044.61 C150_Ch6.2@9806.2,4975.69 ; v2(9918.54,5466.16) 9961.24,5508.85 R161_Ch6.1@9999.08,5508.85 10001.22,5510.99 10044.95,5510.99 C151_Ch6.1@10050.69,5516.72 ; v2(9926,6158) 9926,6113.81 U32_Ch6.3@9926.57,6113.24 ; v2(9954.98,5824.31) R62_Ch6.1@9994.08,5824.31 9994.08,5781.28 C46_Ch6.1@9978.99,5766.2 ; v2(10057.7,5979.61) 10101.2,5979.61 C167_Ch6.2@10106.7,5974.11 ; v2(10139.33,5786.16) C40_Ch6.2@10188.7,5786.16 v2(10188.7,5739.31) ; C37_Ch6.2@10198.91,6110.11 v2(10198.91,6155.75) ; C33_Ch6.2@10262.7,5582.15 10262.7,5585.18 10318.86,5585.18 10340.74,5563.31 v2(10339.49,5563.31) 10339.49,5517.36 R46_Ch6.1@10345.7,5511.15 ; C29_Ch6.2@10264.2,5267.65 v2(10307.39,5267.65) ; C38_Ch6.2@10359.32,5755.65 10375.74,5772.07 v2(10375.74,5794.31) ; C34_Ch6.2@10482.13,6126.15 v2(10482.13,6171.79) ; v2(10485.26,5737.65) C31_Ch6.2@10532.2,5737.65 v2(10532.2,5784.6) ; v2(10494.7,5295.31) C35_Ch6.1@10494.7,5333.09 C35_Ch6.1@10495.7,5334.09 ; v2(10615.7,7098.39) U17.2@10663.57,7098.39 ; C36_Ch6.2@10643.7,5332.09 10640.49,5328.88 C36_Ch6.2@10644.7,5324.67 ; v2(10644.7,5295.31) C36_Ch6.2@10644.7,5324.67 ; C36_Ch6.2@10645.7,5334.09 10644.7,5333.09 C36_Ch6.2@10644.7,5324.67 ; C36_Ch6.2@10647.49,5321.88 C36_Ch6.2@10644.7,5324.67 ; C43_Ch6.2@10652.7,5602.8 C39_Ch6.2@10716.26,5602.8 ; v2(10716.26,5649.74) C39_Ch6.2@10716.26,5602.8 ; v2(10762.76,5602.8) C39_Ch6.2@10716.26,5602.8 ; C90.2@10830.82,7262.2 10892.67,7262.2 C91.2@10892.83,7262.04 10942.95,7262.04 v2(10944.23,7263.32) ; v2(11093.4,7263.32) 11111.81,7281.73 C97.1@11144.8,7281.73 11145.27,7282.2 C96.1@11206.82,7282.2 ; v2(11347.7,5935.23) R79_Ch7.1@11394.08,5935.23 11389.42,5930.57 C55_Ch7.1@11389.42,5878.23 ; v2(11355,6008.08) 11355,6054.83 C166_Ch7.2@11356.45,6056.28 ; v2(11358.7,5089.53) 11358.7,5054.03 C136_Ch7.2@11368.2,5044.53 C150_Ch7.2@11368.2,4975.61 ; U18.2@11373.13,7098.39 v2(11420.99,7098.39) ; v2(11480.54,5466.08) 11523.24,5508.77 R161_Ch7.1@11561.08,5508.77 11563.22,5510.91 11606.95,5510.91 C151_Ch7.1@11612.69,5516.65 ; U32_Ch7.3@11487.81,6113.92 11488,6114.11 v2(11488,6157) ; v2(11516.98,5824.23) R62_Ch7.1@11556.08,5824.23 11556.08,5781.2 C46_Ch7.1@11540.99,5766.12 ; v2(11618.94,5980.28) 11662.45,5980.28 C167_Ch7.2@11667.94,5974.79 ; v2(11701.33,5786.08) C40_Ch7.2@11750.7,5786.08 v2(11750.7,5739.23) ; C37_Ch7.2@11760.91,6110.03 v2(11760.91,6155.67) ; C33_Ch7.2@11824.7,5582.07 11824.7,5585.1 11880.86,5585.1 11902.74,5563.23 v2(11901.49,5563.23) 11901.49,5517.28 R46_Ch7.1@11907.7,5511.07 ; C29_Ch7.2@11826.2,5267.57 v2(11869.39,5267.57) ; C38_Ch7.2@11921.32,5755.57 11937.74,5772 v2(11937.74,5794.23) ; C34_Ch7.2@12044.13,6126.07 v2(12044.13,6171.71) ; v2(12047.26,5737.57) C31_Ch7.2@12094.2,5737.57 v2(12094.2,5784.52) ; v2(12056.7,5295.23) C35_Ch7.1@12056.7,5333.02 C35_Ch7.1@12057.7,5334.02 ; C36_Ch7.2@12205.7,5332.02 12202.49,5328.8 C36_Ch7.2@12206.7,5324.59 ; v2(12206.7,5295.23) C36_Ch7.2@12206.7,5324.59 ; C36_Ch7.2@12207.7,5334.02 12206.7,5333.02 C36_Ch7.2@12206.7,5324.59 ; C36_Ch7.2@12209.49,5321.8 C36_Ch7.2@12206.7,5324.59 ; C43_Ch7.2@12214.7,5602.72 C39_Ch7.2@12278.26,5602.72 ; v2(12278.26,5649.66) C39_Ch7.2@12278.26,5602.72 ; v2(12324.76,5602.72) C39_Ch7.2@12278.26,5602.72 ; v2(12909.7,5935.15) R79_Ch8.1@12956.08,5935.15 12951.42,5930.49 C55_Ch8.1@12951.42,5878.15 ; v2(12917,6008) 12917,6054.76 C166_Ch8.2@12918.45,6056.2 ; v2(12920.7,5089.45) 12920.7,5053.95 C136_Ch8.2@12930.2,5044.45 C150_Ch8.2@12930.2,4975.53 ; v2(13042.54,5466) 13085.24,5508.69 R161_Ch8.1@13123.08,5508.69 13125.22,5510.84 13168.95,5510.84 C151_Ch8.1@13174.69,5516.57 ; U32_Ch8.3@13049.81,6113.84 13050,6114.03 v2(13050,6152) ; v2(13078.98,5824.15) R62_Ch8.1@13118.08,5824.15 13118.08,5781.13 C46_Ch8.1@13102.99,5766.04 ; v2(13180.94,5980.2) 13224.45,5980.2 C167_Ch8.2@13229.94,5974.71 ; v2(13263.33,5786) C40_Ch8.2@13312.7,5786 v2(13312.7,5739.15) ; C37_Ch8.2@13322.91,6109.95 v2(13322.91,6155.59) ; C33_Ch8.2@13386.7,5581.99 13386.7,5585.02 13442.86,5585.02 13464.74,5563.15 v2(13463.49,5563.15) 13463.49,5517.2 R46_Ch8.1@13469.7,5510.99 ; C29_Ch8.2@13388.2,5267.5 v2(13431.39,5267.5) ; C38_Ch8.2@13483.32,5755.5 13499.74,5771.92 v2(13499.74,5794.15) ; C34_Ch8.2@13606.13,6125.99 v2(13606.13,6171.63) ; v2(13609.26,5737.5) C31_Ch8.2@13656.2,5737.5 v2(13656.2,5784.44) ; v2(13618.7,5295.15) C35_Ch8.1@13618.7,5332.94 C35_Ch8.1@13619.7,5333.94 ; C36_Ch8.2@13767.7,5331.94 13764.49,5328.72 C36_Ch8.2@13768.7,5324.51 ; v2(13768.7,5295.15) C36_Ch8.2@13768.7,5324.51 ; C36_Ch8.2@13769.7,5333.94 13768.7,5332.94 C36_Ch8.2@13768.7,5324.51 ; C36_Ch8.2@13771.49,5321.72 C36_Ch8.2@13768.7,5324.51 ; C43_Ch8.2@13776.7,5602.65 C39_Ch8.2@13840.26,5602.65 ; v2(13840.26,5649.58) C39_Ch8.2@13840.26,5602.65 ; v2(13886.76,5602.65) C39_Ch8.2@13840.26,5602.65
  Bottom Layer w25: v1(2021,7503) C142.2@2021,7552.2
  other v1: 2016,6374 2088.1,6374 2160.2,6374 1637,6378 1746.9,6378 1819,6378 2155,7027.9 2155,7100 2155,7172.1 1829,7406 2033,7406 1750,7505 2017,7736
  other v4: 2134,6812.61 2114.31,6851.98 2153.69,6851.98 2134,6891.35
